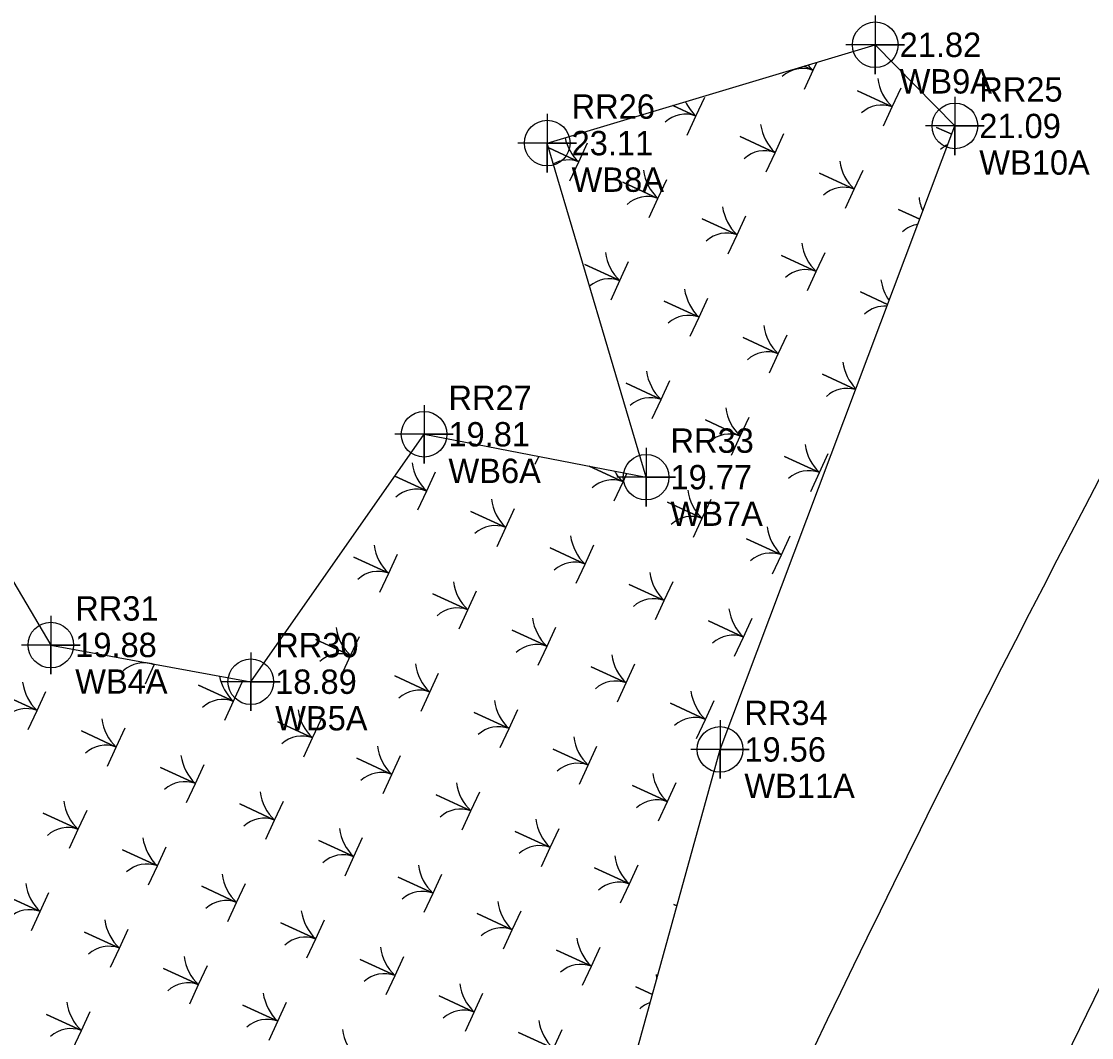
# Model space of a CAD drawing. Extents: x 2532037 to 2533565, y 713396 to 716867.
# Drawn here: x 2532822.3 to 2532932, y 715781.5 to 715885.8 of the extents above; entities that cross this region are included whole.
import ezdxf

# ---------------------------------------------------------------- set-up
doc = ezdxf.new("R2010")
doc.units = 0
for name, color, linetype in [('Exist Environmental Wetland Boundary', 7, 'Continuous'), ('Exist Environmental Wetland Boundary Cogo Comment', 7, 'Continuous'), ('Exist Environmental Wetland Boundary Cogo Elevation', 7, 'Continuous'), ('Exist Environmental Wetland Boundary Cogo Number', 7, 'Continuous'), ('Exist Environmental Wetland Boundary Cogo Point CELL', 7, 'Continuous'), ('Exist Horizontal Alignment', 7, 'Continuous'), ('Exist Right of Way Line', 7, 'Continuous'), ('Exist Roads Soil', 7, 'Continuous'), ('Scratch_Level_1', 7, 'Continuous')]:
    doc.layers.add(name, color=color, linetype=linetype)

msp = doc.modelspace()

# ---------------------------------------------------------------- linework, layer by layer
at = {"layer": 'Exist Environmental Wetland Boundary'}
for p, q in [((2532876.2, 715873.33), (2532909.84, 715883.42)), ((2532909.84, 715883.42), (2532918.01, 715875.09)), ((2532893.92, 715811.11), (2532918.01, 715875.09)), ((2532886.34, 715839.05), (2532876.2, 715873.33)), ((2532806.11, 715854.16), (2532825.29, 715821.82)), ((2532845.8, 715818.06), (2532863.57, 715843.45)), ((2532863.57, 715843.45), (2532886.34, 715839.05)), ((2532825.29, 715821.82), (2532845.8, 715818.06)), ((2532875.12, 715743), (2532893.92, 715811.11))]:
    msp.add_line(p, q, dxfattribs=at)
msp.add_arc((2532826.69, 715820.67), 3.07, 132.1854, 132.7539, dxfattribs=at)
at = {"layer": 'Exist Environmental Wetland Boundary Cogo Point CELL'}
for points in [[(2532909.84, 715886.42), (2532909.84, 715880.42), (2532909.84, 715883.42), (2532912.84, 715883.42), (2532906.84, 715883.42)], [(2532918.01, 715878.09), (2532918.01, 715872.09), (2532918.01, 715875.09), (2532921.01, 715875.09), (2532915.01, 715875.09)], [(2532876.2, 715876.33), (2532876.2, 715870.33), (2532876.2, 715873.33), (2532879.2, 715873.33), (2532873.2, 715873.33)], [(2532863.57, 715846.45), (2532863.57, 715840.45), (2532863.57, 715843.45), (2532866.57, 715843.45), (2532860.57, 715843.45)], [(2532886.34, 715842.05), (2532886.34, 715836.05), (2532886.34, 715839.05), (2532889.34, 715839.05), (2532883.34, 715839.05)], [(2532825.29, 715824.83), (2532825.29, 715818.83), (2532825.29, 715821.82), (2532828.29, 715821.82), (2532822.29, 715821.82)], [(2532845.8, 715821.06), (2532845.8, 715815.06), (2532845.8, 715818.06), (2532848.8, 715818.06), (2532842.8, 715818.06)], [(2532893.92, 715814.11), (2532893.92, 715808.11), (2532893.92, 715811.11), (2532896.92, 715811.11), (2532890.92, 715811.11)]]:
    msp.add_lwpolyline(points, dxfattribs=at)
for centre in [(2532909.84, 715883.42), (2532918.01, 715875.09), (2532876.2, 715873.33), (2532863.57, 715843.45), (2532886.34, 715839.05), (2532825.29, 715821.82), (2532845.8, 715818.06), (2532893.92, 715811.11)]:
    msp.add_circle(centre, 2.34, dxfattribs=at)
at = {"layer": 'Exist Horizontal Alignment'}
msp.add_arc((2534464.19, 715033.98), 1700, 148.47784, 155.05, dxfattribs=at)
at = {"layer": 'Exist Right of Way Line'}
msp.add_arc((2534464.19, 715033.98), 1730, 148.47784, 155.05, dxfattribs=at)
at = {"layer": 'Exist Roads Soil'}
msp.add_lwpolyline([(2533033, 715963.55), (2533014.44, 715935.48), (2532992.67, 715901.09), (2532976.47, 715871.31), (2532962.05, 715845.13), (2532943.27, 715807.99), (2532921.98, 715764.36), (2532902.69, 715724.28), (2532889.07, 715694.2), (2532879.25, 715673.17), (2532870.65, 715655.41), (2532876.57, 715652.01), (2532882.44, 715649.38)], dxfattribs=at)
at = {"layer": 'Scratch_Level_1'}
msp.add_line((2532874.95, 715840.37), (2532875.33, 715841.18), dxfattribs=at)
for points in [[(2532902.54, 715881.23), (2532903.47, 715880.8), (2532903.85, 715881.62)], [(2532902.57, 715878.85), (2532903.47, 715880.8), (2532902.54, 715881.23)], [(2532910.69, 715875.1), (2532911.59, 715877.05), (2532908.01, 715878.7), (2532911.59, 715877.05), (2532912.49, 715879)], [(2532889.09, 715877.19), (2532891.45, 715876.1), (2532892.35, 715878.06)], [(2532890.55, 715874.15), (2532891.45, 715876.1), (2532889.09, 715877.19)], [(2532917.69, 715874.24), (2532916.13, 715874.95), (2532917.69, 715874.24)], [(2532898.67, 715870.4), (2532899.57, 715872.35), (2532895.99, 715874.01), (2532899.57, 715872.35), (2532900.47, 715874.31)], [(2532876.35, 715872.83), (2532879.43, 715871.41), (2532880.33, 715873.36)], [(2532878.53, 715869.46), (2532879.43, 715871.41), (2532876.35, 715872.83)], [(2532906.79, 715866.65), (2532907.69, 715868.61), (2532904.11, 715870.26), (2532907.69, 715868.61), (2532908.59, 715870.56)], [(2532886.65, 715865.71), (2532887.55, 715867.66), (2532883.97, 715869.31), (2532887.55, 715867.66), (2532888.45, 715869.61)], [(2532914.4, 715865.51), (2532912.23, 715866.51), (2532914.4, 715865.51)], [(2532894.77, 715861.96), (2532895.67, 715863.91), (2532892.09, 715865.56), (2532895.67, 715863.91), (2532896.57, 715865.86)], [(2532902.89, 715858.21), (2532903.79, 715860.16), (2532900.21, 715861.81), (2532903.79, 715860.16), (2532904.7, 715862.11)], [(2532882.75, 715857.26), (2532883.65, 715859.22), (2532880.07, 715860.87), (2532883.65, 715859.22), (2532884.55, 715861.17)], [(2532890.87, 715853.51), (2532891.77, 715855.47), (2532888.19, 715857.12), (2532891.77, 715855.47), (2532892.68, 715857.42)], [(2532911.11, 715856.78), (2532908.33, 715858.07), (2532911.11, 715856.78)], [(2532898.99, 715849.76), (2532899.9, 715851.72), (2532896.31, 715853.37), (2532899.9, 715851.72), (2532900.8, 715853.67)], [(2532886.97, 715845.07), (2532887.88, 715847.02), (2532884.29, 715848.68), (2532887.88, 715847.02), (2532888.78, 715848.97)], [(2532907.83, 715848.05), (2532904.44, 715849.62), (2532907.83, 715848.05)], [(2532895.1, 715841.32), (2532896, 715843.27), (2532892.42, 715844.93), (2532896, 715843.27), (2532896.9, 715845.22)], [(2532903.22, 715837.57), (2532904.12, 715839.52), (2532900.54, 715841.18), (2532904.12, 715839.52), (2532905.02, 715841.48)], [(2532883.08, 715836.63), (2532883.98, 715838.58), (2532880.5, 715840.18)], [(2532880.5, 715840.18), (2532883.98, 715838.58), (2532884.37, 715839.43)], [(2532860.56, 715839.15), (2532863.84, 715837.63), (2532864.74, 715839.58)], [(2532862.93, 715835.68), (2532863.84, 715837.63), (2532860.56, 715839.15)], [(2532891.2, 715832.88), (2532892.1, 715834.83), (2532888.52, 715836.48), (2532892.1, 715834.83), (2532893, 715836.78)], [(2532871.06, 715831.93), (2532871.96, 715833.88), (2532868.38, 715835.54), (2532871.96, 715833.88), (2532872.86, 715835.83)], [(2532899.32, 715829.13), (2532900.22, 715831.08), (2532896.64, 715832.73), (2532900.22, 715831.08), (2532901.12, 715833.03)], [(2532859.04, 715827.24), (2532859.94, 715829.19), (2532856.36, 715830.84), (2532859.94, 715829.19), (2532860.84, 715831.14)], [(2532879.18, 715828.18), (2532880.08, 715830.13), (2532876.5, 715831.79), (2532880.08, 715830.13), (2532880.98, 715832.09)], [(2532887.3, 715824.43), (2532888.2, 715826.38), (2532884.62, 715828.04), (2532888.2, 715826.38), (2532889.1, 715828.34)], [(2532867.16, 715823.49), (2532868.06, 715825.44), (2532864.48, 715827.09), (2532868.06, 715825.44), (2532868.96, 715827.39)], [(2532895.42, 715820.68), (2532896.32, 715822.63), (2532892.74, 715824.29), (2532896.32, 715822.63), (2532897.22, 715824.59)], [(2532875.28, 715819.74), (2532876.18, 715821.69), (2532872.6, 715823.34), (2532876.18, 715821.69), (2532877.08, 715823.64)], [(2532855.14, 715818.79), (2532856.04, 715820.74), (2532852.46, 715822.4), (2532856.04, 715820.74), (2532856.94, 715822.7)], [(2532835, 715817.85), (2532835.9, 715819.8), (2532835.61, 715819.93)], [(2532835.61, 715819.93), (2532835.9, 715819.8), (2532835.93, 715819.87)], [(2532883.4, 715815.99), (2532884.3, 715817.94), (2532880.72, 715819.59), (2532884.3, 715817.94), (2532885.2, 715819.89)], [(2532843.12, 715814.1), (2532844.02, 715816.05), (2532840.44, 715817.7), (2532844.02, 715816.05), (2532844.92, 715818)], [(2532863.26, 715815.04), (2532864.16, 715816.99), (2532860.58, 715818.65), (2532864.16, 715816.99), (2532865.06, 715818.95)], [(2532822.98, 715813.15), (2532823.88, 715815.1), (2532820.3, 715816.76), (2532823.88, 715815.1), (2532824.78, 715817.05)], [(2532891.52, 715812.24), (2532892.42, 715814.19), (2532888.84, 715815.84), (2532892.42, 715814.19), (2532893.32, 715816.14)], [(2532871.38, 715811.29), (2532872.28, 715813.24), (2532868.7, 715814.9), (2532872.28, 715813.24), (2532873.18, 715815.2)], [(2532851.24, 715810.35), (2532852.14, 715812.3), (2532848.56, 715813.95), (2532852.14, 715812.3), (2532853.04, 715814.25)], [(2532831.1, 715809.4), (2532832, 715811.35), (2532828.42, 715813.01), (2532832, 715811.35), (2532832.9, 715813.31)], [(2532879.5, 715807.54), (2532880.4, 715809.5), (2532876.82, 715811.15), (2532880.4, 715809.5), (2532881.3, 715811.45)], [(2532859.36, 715806.6), (2532860.26, 715808.55), (2532856.68, 715810.2), (2532860.26, 715808.55), (2532861.16, 715810.5)], [(2532839.22, 715805.65), (2532840.12, 715807.6), (2532836.54, 715809.26), (2532840.12, 715807.6), (2532841.02, 715809.56)], [(2532887.62, 715803.79), (2532888.52, 715805.75), (2532884.94, 715807.4), (2532888.52, 715805.75), (2532889.43, 715807.7)], [(2532847.34, 715801.9), (2532848.24, 715803.85), (2532844.66, 715805.51), (2532848.24, 715803.85), (2532849.14, 715805.81)], [(2532867.48, 715802.85), (2532868.38, 715804.8), (2532864.8, 715806.45), (2532868.38, 715804.8), (2532869.28, 715806.75)], [(2532827.2, 715800.96), (2532828.1, 715802.91), (2532824.52, 715804.56), (2532828.1, 715802.91), (2532829, 715804.86)], [(2532875.6, 715799.1), (2532876.5, 715801.05), (2532872.92, 715802.7), (2532876.5, 715801.05), (2532877.41, 715803)], [(2532855.46, 715798.15), (2532856.36, 715800.11), (2532852.78, 715801.76), (2532856.36, 715800.11), (2532857.26, 715802.06)], [(2532835.32, 715797.21), (2532836.22, 715799.16), (2532832.64, 715800.81), (2532836.22, 715799.16), (2532837.12, 715801.11)], [(2532883.73, 715795.35), (2532884.63, 715797.3), (2532881.04, 715798.95), (2532884.63, 715797.3), (2532885.53, 715799.25)], [(2532863.58, 715794.4), (2532864.49, 715796.36), (2532860.9, 715798.01), (2532864.49, 715796.36), (2532865.39, 715798.31)], [(2532843.44, 715793.46), (2532844.34, 715795.41), (2532840.76, 715797.06), (2532844.34, 715795.41), (2532845.25, 715797.36)], [(2532823.3, 715792.51), (2532824.2, 715794.46), (2532820.62, 715796.12), (2532824.2, 715794.46), (2532825.1, 715796.42)], [(2532889.49, 715795.06), (2532889.17, 715795.21), (2532889.49, 715795.06)], [(2532871.71, 715790.65), (2532872.61, 715792.61), (2532869.02, 715794.26), (2532872.61, 715792.61), (2532873.51, 715794.56)], [(2532831.42, 715788.76), (2532832.32, 715790.72), (2532828.74, 715792.37), (2532832.32, 715790.72), (2532833.23, 715792.67)], [(2532851.56, 715789.71), (2532852.47, 715791.66), (2532848.88, 715793.31), (2532852.47, 715791.66), (2532853.37, 715793.61)], [(2532879.83, 715786.9), (2532880.73, 715788.86), (2532877.15, 715790.51), (2532880.73, 715788.86), (2532881.63, 715790.81)], [(2532859.69, 715785.96), (2532860.59, 715787.91), (2532857, 715789.56), (2532860.59, 715787.91), (2532861.49, 715789.86)], [(2532839.54, 715785.01), (2532840.45, 715786.97), (2532836.86, 715788.62), (2532840.45, 715786.97), (2532841.35, 715788.92)], [(2532867.81, 715782.21), (2532868.71, 715784.16), (2532865.13, 715785.82), (2532868.71, 715784.16), (2532869.61, 715786.11)], [(2532886.98, 715785.97), (2532885.27, 715786.76), (2532886.98, 715785.97)], [(2532847.67, 715781.26), (2532848.57, 715783.22), (2532844.98, 715784.87), (2532848.57, 715783.22), (2532849.47, 715785.17)], [(2532827.52, 715780.32), (2532828.43, 715782.27), (2532824.84, 715783.92), (2532828.43, 715782.27), (2532829.33, 715784.22)], [(2532875.93, 715778.46), (2532876.83, 715780.41), (2532873.25, 715782.07), (2532876.83, 715780.41), (2532877.73, 715782.36)]]:
    msp.add_lwpolyline(points, dxfattribs=at)
for centre, radius, start, end in [((2532902.39, 715877.92), 3.07, 69.3593, 132.7539), ((2532906.76, 715884.3), 4.81, 217.8479, 226.8412), ((2532914.88, 715880.56), 4.81, 187.3464, 226.8412), ((2532894.74, 715879.61), 4.81, 204.9536, 226.8412), ((2532910.51, 715874.17), 3.07, 69.3593, 132.7539), ((2532890.37, 715873.23), 3.07, 69.3593, 132.7539), ((2532902.86, 715875.86), 4.81, 187.3464, 226.8412), ((2532882.72, 715874.91), 4.81, 192.4756, 226.8412), ((2532918.63, 715870.42), 3.07, 115.7048, 132.7539), ((2532898.49, 715869.48), 3.07, 69.3593, 132.7539), ((2532878.35, 715868.53), 3.07, 69.3593, 119.5417), ((2532890.84, 715871.17), 4.81, 187.3464, 226.8412), ((2532910.98, 715872.11), 4.81, 187.3464, 226.8412), ((2532906.61, 715865.73), 3.07, 69.3593, 132.7539), ((2532886.47, 715864.78), 3.07, 69.3593, 132.7539), ((2532919.1, 715868.36), 4.81, 187.3464, 204.451), ((2532898.96, 715867.42), 4.81, 187.3464, 226.8412), ((2532894.59, 715861.03), 3.07, 69.3593, 132.7539), ((2532914.73, 715861.98), 3.07, 99.6775, 132.7539), ((2532907.08, 715863.67), 4.81, 187.3464, 226.8412), ((2532886.94, 715862.72), 4.81, 187.3464, 226.8412), ((2532902.71, 715857.28), 3.07, 69.3593, 132.7539), ((2532882.57, 715856.34), 3.07, 69.3593, 131.1989), ((2532915.2, 715859.92), 4.81, 187.3464, 214.8861), ((2532895.06, 715858.97), 4.81, 187.3464, 226.8412), ((2532910.83, 715853.53), 3.07, 85.9828, 132.7539), ((2532890.69, 715852.59), 3.07, 69.3593, 132.7539), ((2532903.18, 715855.22), 4.81, 187.3464, 226.8412), ((2532898.81, 715848.84), 3.07, 69.3593, 132.7539), ((2532911.3, 715851.47), 4.81, 187.3464, 224.1409), ((2532891.16, 715850.53), 4.81, 187.3464, 226.8412), ((2532906.93, 715845.09), 3.07, 73.2213, 132.7539), ((2532886.79, 715844.14), 3.07, 69.3593, 132.7539), ((2532899.28, 715846.78), 4.81, 187.3464, 226.8412), ((2532894.91, 715840.4), 3.07, 69.3593, 132.7539), ((2532907.41, 715843.03), 4.81, 187.3464, 226.8412), ((2532867.12, 715841.14), 4.81, 187.3464, 226.8412), ((2532882.89, 715835.7), 3.07, 69.3593, 132.7539), ((2532887.26, 715842.08), 4.81, 210.0216, 226.8412), ((2532903.03, 715836.65), 3.07, 69.3593, 132.7539), ((2532862.75, 715834.75), 3.07, 69.3593, 132.7539), ((2532895.39, 715838.33), 4.81, 187.3464, 226.8412), ((2532875.24, 715837.39), 4.81, 187.3464, 226.8412), ((2532891.01, 715831.95), 3.07, 69.3593, 132.7539), ((2532870.87, 715831.01), 3.07, 69.3593, 132.7539), ((2532903.51, 715834.58), 4.81, 187.3464, 226.8412), ((2532883.37, 715833.64), 4.81, 187.3464, 226.8412), ((2532863.22, 715832.69), 4.81, 187.3464, 226.8412), ((2532899.14, 715828.2), 3.07, 69.3593, 132.7539), ((2532879, 715827.26), 3.07, 69.3593, 132.7539), ((2532858.85, 715826.31), 3.07, 69.3593, 132.7539), ((2532891.49, 715829.89), 4.81, 187.3464, 226.8412), ((2532871.35, 715828.94), 4.81, 187.3464, 226.8412), ((2532866.98, 715822.56), 3.07, 69.3593, 132.7539), ((2532887.12, 715823.51), 3.07, 69.3593, 132.7539), ((2532879.47, 715825.19), 4.81, 187.3464, 226.8412), ((2532899.61, 715826.14), 4.81, 187.3464, 226.8412), ((2532859.33, 715824.25), 4.81, 187.3464, 226.8412), ((2532895.24, 715819.76), 3.07, 69.3593, 132.7539), ((2532875.1, 715818.81), 3.07, 69.3593, 132.7539), ((2532854.96, 715817.87), 3.07, 69.3593, 132.7539), ((2532887.59, 715821.44), 4.81, 187.3464, 226.8412), ((2532834.81, 715816.92), 3.07, 69.3593, 132.7539), ((2532839.18, 715823.3), 4.81, 225.1674, 226.8412), ((2532867.45, 715820.5), 4.81, 187.3464, 226.8412), ((2532827.17, 715818.61), 4.81, 187.3464, 226.8412), ((2532847.31, 715819.55), 4.81, 190.8721, 226.8412), ((2532883.22, 715815.06), 3.07, 69.3593, 132.7539), ((2532863.08, 715814.12), 3.07, 69.3593, 132.7539), ((2532895.71, 715817.7), 4.81, 187.3464, 226.8412), ((2532842.94, 715813.17), 3.07, 69.3593, 132.7539), ((2532875.57, 715816.75), 4.81, 187.3464, 226.8412), ((2532822.79, 715812.23), 3.07, 69.3593, 132.7539), ((2532855.43, 715815.8), 4.81, 187.3464, 226.8412), ((2532835.29, 715814.86), 4.81, 187.3464, 226.8412), ((2532891.34, 715811.31), 3.07, 69.3593, 132.7539), ((2532851.06, 715809.42), 3.07, 69.3593, 132.7539), ((2532871.2, 715810.37), 3.07, 69.3593, 132.7539), ((2532883.69, 715813), 4.81, 187.3464, 226.8412), ((2532830.92, 715808.48), 3.07, 69.3593, 132.7539), ((2532863.55, 715812.05), 4.81, 187.3464, 226.8412), ((2532843.41, 715811.11), 4.81, 187.3464, 226.8412), ((2532879.32, 715806.62), 3.07, 69.3593, 132.7539), ((2532859.18, 715805.67), 3.07, 69.3593, 132.7539), ((2532891.81, 715809.25), 4.81, 187.3464, 226.8412), ((2532839.04, 715804.73), 3.07, 69.3593, 132.7539), ((2532871.67, 715808.31), 4.81, 187.3464, 226.8412), ((2532831.39, 715806.41), 4.81, 187.3464, 226.8412), ((2532851.53, 715807.36), 4.81, 187.3464, 226.8412), ((2532887.44, 715802.87), 3.07, 69.3593, 132.7539), ((2532867.3, 715801.92), 3.07, 69.3593, 132.7539), ((2532847.16, 715800.98), 3.07, 69.3593, 132.7539), ((2532879.79, 715804.56), 4.81, 187.3464, 226.8412), ((2532827.02, 715800.03), 3.07, 69.3593, 132.7539), ((2532859.65, 715803.61), 4.81, 187.3464, 226.8412), ((2532839.51, 715802.66), 4.81, 187.3464, 226.8412), ((2532855.28, 715797.23), 3.07, 69.3593, 132.7539), ((2532875.42, 715798.17), 3.07, 69.3593, 132.7539), ((2532835.14, 715796.28), 3.07, 69.3593, 132.7539), ((2532867.77, 715799.86), 4.81, 187.3464, 226.8412), ((2532887.91, 715800.81), 4.81, 187.3464, 226.8412), ((2532847.63, 715798.92), 4.81, 187.3464, 226.8412), ((2532827.49, 715797.97), 4.81, 187.3464, 226.8412), ((2532883.54, 715794.42), 3.07, 69.3593, 132.7539), ((2532863.4, 715793.48), 3.07, 69.3593, 132.7539), ((2532843.26, 715792.53), 3.07, 69.3593, 132.7539), ((2532875.89, 715796.11), 4.81, 187.3464, 226.8412), ((2532823.12, 715791.59), 3.07, 69.3593, 132.7539), ((2532855.75, 715795.17), 4.81, 187.3464, 226.8412), ((2532835.61, 715794.22), 4.81, 187.3464, 226.8412), ((2532871.52, 715789.73), 3.07, 69.3593, 132.7539), ((2532851.38, 715788.78), 3.07, 69.3593, 132.7539), ((2532884.02, 715792.36), 4.81, 187.3464, 226.8412), ((2532831.24, 715787.84), 3.07, 69.3593, 132.7539), ((2532863.87, 715791.42), 4.81, 187.3464, 226.8412), ((2532843.73, 715790.47), 4.81, 187.3464, 226.8412), ((2532879.64, 715785.98), 3.07, 69.3593, 132.7539), ((2532839.36, 715784.09), 3.07, 69.3593, 132.7539), ((2532859.5, 715785.03), 3.07, 69.3593, 132.7539), ((2532892.14, 715788.61), 4.81, 187.3464, 191.9059), ((2532851.85, 715786.72), 4.81, 187.3464, 226.8412), ((2532872, 715787.67), 4.81, 187.3464, 226.8412), ((2532831.71, 715785.78), 4.81, 187.3464, 226.8412), ((2532887.77, 715782.23), 3.07, 109.3472, 132.7539), ((2532867.62, 715781.28), 3.07, 69.3593, 132.7539), ((2532847.48, 715780.34), 3.07, 69.3593, 132.7539), ((2532880.12, 715783.92), 4.81, 187.3464, 226.8412), ((2532827.34, 715779.39), 3.07, 69.3593, 132.7539), ((2532859.98, 715782.97), 4.81, 187.3464, 226.8412)]:
    msp.add_arc(centre, radius, start, end, dxfattribs=at)

# ---------------------------------------------------------------- texts
at = {"layer": 'Exist Environmental Wetland Boundary Cogo Comment'}
for s, p in [('WB9A', (2532912.34, 715878.42)), ('WB10A', (2532920.51, 715870.09)), ('WB8A', (2532878.7, 715868.33)), ('WB6A', (2532866.07, 715838.45)), ('WB7A', (2532888.84, 715834.05)), ('WB4A', (2532827.79, 715816.83)), ('WB5A', (2532848.3, 715813.06)), ('WB11A', (2532896.42, 715806.11))]:
    msp.add_text(s, height=2.5, dxfattribs=at).set_placement(p)
at = {"layer": 'Exist Environmental Wetland Boundary Cogo Elevation'}
for s, p in [('21.82', (2532912.34, 715882.17)), ('21.09', (2532920.51, 715873.84)), ('23.11', (2532878.7, 715872.08)), ('19.81', (2532866.07, 715842.2)), ('19.77', (2532888.84, 715837.8)), ('19.88', (2532827.79, 715820.58)), ('18.89', (2532848.3, 715816.81)), ('19.56', (2532896.42, 715809.86))]:
    msp.add_text(s, height=2.5, dxfattribs=at).set_placement(p)
at = {"layer": 'Exist Environmental Wetland Boundary Cogo Number'}
for s, p in [('RR25', (2532920.51, 715877.59)), ('RR26', (2532878.7, 715875.83)), ('RR27', (2532866.07, 715845.95)), ('RR33', (2532888.84, 715841.55)), ('RR31', (2532827.79, 715824.33)), ('RR30', (2532848.3, 715820.56)), ('RR34', (2532896.42, 715813.61))]:
    msp.add_text(s, height=2.5, dxfattribs=at).set_placement(p)

doc.saveas('drawing.dxf')
